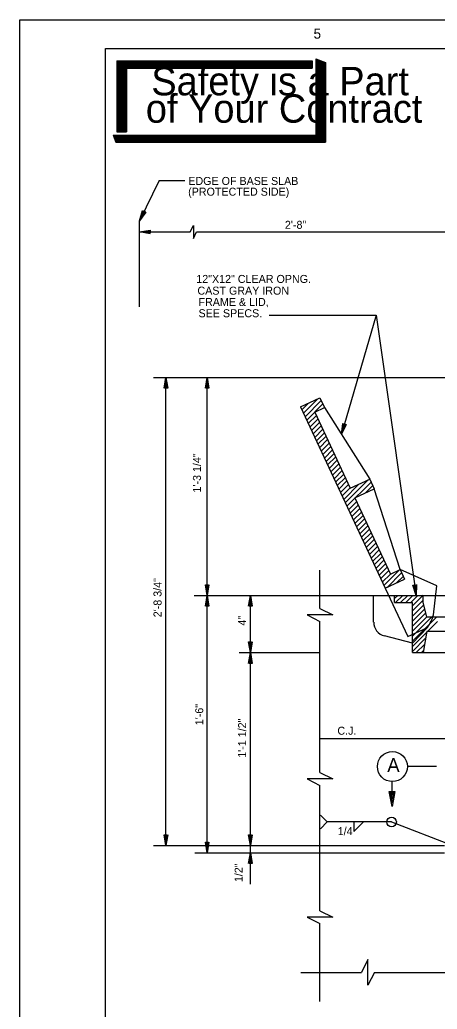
# Model space of a CAD drawing. Extents: x 0.1 to 13.5, y 0.1 to 9.5.
# Drawn here: x 0.13 to 2.56, y 3.69 to 9.46 of the extents above; entities that cross this region are included whole.
import ezdxf

# ---------------------------------------------------------------- set-up
doc = ezdxf.new("R2010")
doc.units = 0
for name, color, linetype in [('Level 1', 7, 'Continuous'), ('Level 13', 7, 'Continuous'), ('Level 2', 7, 'Continuous'), ('Level 25', 7, 'Continuous'), ('Level 3', 7, 'Continuous'), ('Level 50', 7, 'Continuous')]:
    doc.layers.add(name, color=color, linetype=linetype)

msp = doc.modelspace()

# ---------------------------------------------------------------- linework, layer by layer
at = {"layer": 'Level 1'}
for p, q in [((1.8506, 9.2306), (1.8506, 8.7859)), ((1.8506, 9.2306), (1.9063, 9.2099)), ((1.8543, 9.2292), (1.8543, 8.7442)), ((0.6906, 9.2182), (1.8296, 9.2182)), ((0.6906, 9.2182), (0.6906, 8.8046)), ((0.6906, 9.2129), (1.8296, 9.2129)), ((0.6906, 9.2079), (1.8296, 9.2079)), ((0.6906, 9.2026), (1.8296, 9.2026)), ((0.6906, 9.1972), (1.8296, 9.1972)), ((0.6906, 9.1922), (1.8296, 9.1922)), ((0.6906, 9.1869), (1.8296, 9.1869)), ((0.6906, 9.1819), (1.8296, 9.1819)), ((0.6959, 9.2182), (0.6959, 8.8046)), ((0.7009, 9.2182), (0.7009, 8.8046)), ((0.7063, 9.2182), (0.7063, 8.8046)), ((0.7113, 9.2182), (0.7113, 8.8046)), ((0.7166, 9.2182), (0.7166, 8.8046)), ((0.7219, 9.2182), (0.7219, 8.8046)), ((0.7269, 9.2182), (0.7269, 8.8046)), ((0.7323, 9.2182), (0.7323, 8.8046)), ((0.7376, 9.2182), (0.7376, 8.8046)), ((0.7426, 9.2182), (0.7426, 8.8046)), ((0.7463, 9.1766), (1.8296, 9.1766)), ((0.7463, 9.1766), (0.7463, 8.8046)), ((1.8296, 9.2182), (1.8296, 9.1766)), ((1.8593, 9.2272), (1.8593, 8.7442)), ((1.8646, 9.2252), (1.8646, 8.7442)), ((1.8699, 9.2232), (1.8699, 8.7442)), ((1.8749, 9.2216), (1.8749, 8.7442)), ((1.8803, 9.2196), (1.8803, 8.7442)), ((1.8853, 9.2176), (1.8853, 8.7442)), ((1.8906, 9.2156), (1.8906, 8.7442)), ((1.8959, 9.2139), (1.8959, 8.7442)), ((1.9009, 9.2099), (1.9009, 8.7442)), ((1.9063, 9.2099), (1.9063, 8.7442)), ((0.6696, 8.7859), (1.8506, 8.7859)), ((0.6696, 8.7859), (0.6849, 8.7442)), ((0.6716, 8.7806), (1.8543, 8.7806)), ((0.6733, 8.7756), (1.8543, 8.7756)), ((0.6753, 8.7702), (1.8543, 8.7702)), ((0.6906, 8.8046), (0.7463, 8.8046)), ((0.6773, 8.7649), (1.8543, 8.7649)), ((0.6793, 8.7599), (1.8543, 8.7599)), ((0.6813, 8.7546), (1.8543, 8.7546)), ((0.6829, 8.7496), (1.8543, 8.7496)), ((0.6849, 8.7442), (1.9063, 8.7442))]:
    msp.add_line(p, q, dxfattribs=at)
for points in [[(0.125, 9.4583), (13.4583, 9.4583), (13.4583, 0.125), (0.125, 0.125)], [(0.625, 9.2917), (13.2917, 9.2917), (13.2917, 0.2917), (0.625, 0.2917)]]:
    msp.add_lwpolyline(points, close=True, dxfattribs=at)
at = {"layer": 'Level 13'}
for points in [[(1.1179, 8.2214), (1.1365, 8.2589), (1.1365, 8.184), (1.1553, 8.2214)], [(1.8741, 6.0263), (1.9491, 5.989), (1.7993, 5.989), (1.8741, 5.9515)], [(1.8741, 5.0704), (1.9491, 5.0332), (1.7993, 5.0332), (1.8741, 4.9957)], [(1.8741, 4.2652), (1.9491, 4.228), (1.7993, 4.228), (1.8741, 4.1905)], [(2.1915, 3.9056), (2.1542, 3.8306), (2.1542, 3.9805), (2.1167, 3.9056)]]:
    msp.add_lwpolyline(points, dxfattribs=at)
at = {"layer": 'Level 25'}
for p, q in [((0.9378, 8.5209), (0.8229, 8.2865)), ((0.9378, 8.5209), (1.0873, 8.5209)), ((0.8229, 7.7843), (0.8229, 8.2865)), ((0.8229, 8.2214), (1.1179, 8.2214)), ((1.1553, 8.2214), (3.0596, 8.2214)), ((1.5787, 7.7375), (2.202, 7.7375)), ((2.202, 7.7375), (1.9993, 7.0424)), ((2.202, 7.7375), (2.4353, 6.1027)), ((0.9038, 7.3735), (2.6846, 7.3735)), ((0.9766, 4.6444), (0.9766, 7.3735)), ((1.2169, 6.1027), (1.2169, 7.3735)), ((1.7614, 7.2017), (1.8747, 7.2545)), ((1.8073, 7.2231), (1.7692, 7.185)), ((1.8625, 7.2488), (1.7786, 7.1649)), ((1.882, 7.2389), (1.788, 7.1448)), ((1.8914, 7.2188), (1.7973, 7.1248)), ((1.8747, 7.2545), (1.9011, 7.1979)), ((1.7614, 7.2017), (2.2545, 6.1444)), ((1.8537, 7.1517), (1.8067, 7.1047)), ((1.8445, 7.1715), (1.9011, 7.1979)), ((1.8445, 7.1715), (1.8684, 7.1203)), ((1.8445, 7.1715), (2.0514, 6.7278)), ((1.9011, 7.1979), (2.1647, 6.7806)), ((1.8631, 7.1316), (1.8161, 7.0846)), ((1.8725, 7.1115), (1.8254, 7.0645)), ((1.8819, 7.0914), (1.8348, 7.0444)), ((1.8912, 7.0713), (1.8442, 7.0243)), ((1.9006, 7.0512), (1.8535, 7.0042)), ((1.91, 7.0311), (1.8629, 6.9841)), ((1.9193, 7.0111), (1.8723, 6.964)), ((1.9287, 6.991), (1.8816, 6.9439)), ((1.9381, 6.9709), (1.891, 6.9238)), ((1.9474, 6.9508), (1.9004, 6.9037)), ((1.9568, 6.9307), (1.9098, 6.8836)), ((1.9662, 6.9106), (1.9191, 6.8635)), ((1.9755, 6.8905), (1.9285, 6.8435)), ((1.9849, 6.8704), (1.9379, 6.8234)), ((1.9943, 6.8503), (1.9472, 6.8033)), ((2.0036, 6.8302), (1.9566, 6.7832)), ((2.013, 6.8101), (1.966, 6.7631)), ((2.0224, 6.79), (1.9753, 6.743)), ((2.0318, 6.7699), (1.9847, 6.7229)), ((2.0411, 6.7498), (1.9941, 6.7028)), ((2.1012, 6.751), (2.0128, 6.6626)), ((2.1564, 6.7767), (2.0222, 6.6425)), ((2.1726, 6.7635), (2.0316, 6.6224)), ((2.0514, 6.7278), (2.1647, 6.7806)), ((2.1647, 6.7806), (2.1911, 6.7239)), ((2.0505, 6.7298), (2.0035, 6.6827)), ((2.0778, 6.6711), (2.1911, 6.7239)), ((2.182, 6.7434), (2.1376, 6.699)), ((2.3413, 6.2538), (2.1911, 6.7239)), ((2.088, 6.6494), (2.0409, 6.6023)), ((2.0778, 6.6711), (2.2847, 6.2274)), ((2.0973, 6.6293), (2.0503, 6.5823)), ((2.1067, 6.6092), (2.0597, 6.5622)), ((2.1161, 6.5891), (2.069, 6.5421)), ((2.1254, 6.569), (2.0784, 6.522)), ((2.1348, 6.5489), (2.0878, 6.5019)), ((2.1442, 6.5288), (2.0971, 6.4818)), ((2.1535, 6.5087), (2.1065, 6.4617)), ((2.1629, 6.4886), (2.1159, 6.4416)), ((2.1723, 6.4685), (2.1253, 6.4215)), ((2.1816, 6.4484), (2.1346, 6.4014)), ((2.191, 6.4283), (2.144, 6.3813)), ((2.2004, 6.4082), (2.1534, 6.3612)), ((2.2098, 6.3882), (2.1627, 6.3411)), ((2.2191, 6.3681), (2.1721, 6.321)), ((2.2285, 6.348), (2.1815, 6.3009)), ((2.2379, 6.3279), (2.1908, 6.2809)), ((2.2472, 6.3078), (2.2002, 6.2608)), ((2.2566, 6.2877), (2.2096, 6.2407)), ((1.8741, 6.0263), (1.8741, 6.2501)), ((2.266, 6.2676), (2.2189, 6.2206)), ((2.2753, 6.2475), (2.2283, 6.2005)), ((2.3399, 6.2531), (2.2471, 6.1603)), ((2.3505, 6.2342), (2.2659, 6.1497)), ((2.2847, 6.2274), (2.3413, 6.2538)), ((2.3413, 6.2538), (2.3678, 6.1972)), ((2.5561, 6.1592), (2.3413, 6.2538)), ((2.2847, 6.2274), (2.2377, 6.1804)), ((2.2545, 6.1444), (2.3678, 6.1972)), ((2.3598, 6.2141), (2.3211, 6.1754)), ((2.2545, 6.1444), (2.3859, 5.8625)), ((2.5363, 5.9897), (2.5561, 6.1592)), ((1.1421, 6.1027), (1.8741, 6.1027)), ((1.2169, 4.6027), (1.2169, 6.1027)), ((1.4687, 5.7694), (1.4687, 6.1027)), ((1.8741, 6.1027), (2.4763, 6.1027)), ((2.1875, 5.9471), (2.1875, 6.1027)), ((2.3096, 6.061), (2.3096, 6.1027)), ((2.3275, 6.1027), (2.3096, 6.0848)), ((2.3096, 6.061), (2.4138, 6.061)), ((2.357, 6.1027), (2.3153, 6.061)), ((2.3864, 6.1027), (2.3448, 6.061)), ((2.4159, 6.1027), (2.3742, 6.061)), ((2.4454, 6.1027), (2.4037, 6.061)), ((2.4763, 6.1042), (2.4138, 6.0417)), ((2.4763, 6.0747), (2.4138, 6.0122)), ((2.4138, 5.7694), (2.4138, 6.061)), ((2.4763, 6.061), (2.4763, 6.1027)), ((2.4763, 6.1027), (2.5495, 6.1027)), ((2.4971, 5.9777), (2.4763, 6.061)), ((2.5495, 6.1027), (2.6846, 6.1027)), ((2.4795, 6.0484), (2.4138, 5.9828)), ((2.4854, 6.0248), (2.4138, 5.9533)), ((2.4913, 6.0013), (2.4138, 5.9238)), ((1.8741, 5.0704), (1.8741, 5.9515)), ((2.4971, 5.9777), (2.4138, 5.8944)), ((2.5266, 5.9777), (2.4138, 5.8649)), ((2.5561, 5.9777), (2.4138, 5.8354)), ((2.5596, 5.9518), (2.4138, 5.806)), ((2.4971, 5.9777), (2.6846, 5.9777)), ((2.3859, 5.8625), (2.5021, 5.9166)), ((2.4135, 5.824), (2.5021, 5.9166)), ((2.4971, 5.8944), (2.4763, 5.7694)), ((2.4971, 5.8944), (2.6846, 5.8944)), ((2.4135, 5.824), (2.2499, 5.8665)), ((2.4902, 5.8529), (2.4138, 5.7765)), ((1.4034, 5.7694), (1.8741, 5.7694)), ((1.4687, 4.6444), (1.4687, 5.7694)), ((2.4138, 5.7694), (2.6846, 5.7694)), ((2.4843, 5.8176), (2.4361, 5.7694)), ((2.4785, 5.7822), (2.4656, 5.7694)), ((1.8741, 5.2694), (5.7074, 5.2694)), ((1.8741, 4.2652), (1.8741, 4.9957)), ((1.9167, 4.7824), (1.8769, 4.8223)), ((1.9167, 4.7824), (1.8769, 4.7427)), ((2.2918, 4.7824), (1.9167, 4.7824)), ((2.0722, 4.783), (2.0722, 4.7268)), ((2.0722, 4.7268), (2.128, 4.7826)), ((2.2918, 4.7824), (2.643, 4.647)), ((0.9038, 4.6444), (2.6013, 4.6444)), ((1.4687, 4.6027), (1.4687, 4.6444)), ((1.1453, 4.6027), (2.6013, 4.6027)), ((1.4687, 4.4202), (1.4687, 4.6027)), ((1.8741, 3.7351), (1.8741, 4.1905)), ((1.7622, 3.9056), (2.1167, 3.9056)), ((2.1915, 3.9056), (3.1524, 3.9056))]:
    msp.add_line(p, q, dxfattribs=at)
msp.add_circle((2.2918, 4.7824), 0.0281, dxfattribs=at)
for centre, radius, start, end in [((2.2709, 5.9471), 0.0833, 180, 255.43423), ((2.2735, 6.0684), 0.2744, 326.4322, 343.33101)]:
    msp.add_arc(centre, radius, start, end, dxfattribs=at)
at = {"layer": 'Level 3'}
for p, q in [((2.5544, 5.1051), (2.3823, 5.1051)), ((2.2949, 4.9593), (2.2949, 5.0176))]:
    msp.add_line(p, q, dxfattribs=at)
msp.add_lwpolyline([(2.3072, 4.9593), (2.3115, 4.9593), (2.2949, 4.8718), (2.2786, 4.9593), (2.3072, 4.9593), (2.2952, 4.8941), (2.2835, 4.9551), (2.3024, 4.9551), (2.2952, 4.9161), (2.2887, 4.951), (2.2974, 4.951), (2.2952, 4.9385), (2.2936, 4.9468)], dxfattribs=at)
msp.add_circle((2.2966, 5.1051), 0.0875, dxfattribs=at)
at = {"layer": 'Level 50'}
for p, q in [((0.8229, 8.2865), (0.8229, 8.2865)), ((0.8305, 8.302), (0.8305, 8.302)), ((0.8229, 8.2214), (0.8229, 8.2214)), ((0.8403, 8.2214), (0.8403, 8.2214)), ((0.9766, 7.3735), (0.9766, 7.3735)), ((0.9766, 7.3562), (0.9766, 7.3562)), ((1.2169, 7.3735), (1.2169, 7.3735)), ((1.2169, 7.3562), (1.2169, 7.3562)), ((1.9993, 7.0424), (1.9993, 7.0424)), ((2.0042, 7.059), (2.0042, 7.059)), ((1.2169, 6.12), (1.2169, 6.12)), ((2.4329, 6.1199), (2.4329, 6.1199)), ((1.2169, 6.1027), (1.2169, 6.1027)), ((1.2169, 6.1027), (1.2169, 6.1027)), ((1.2169, 6.0854), (1.2169, 6.0854)), ((1.4687, 6.1027), (1.4687, 6.1027)), ((1.4687, 6.0854), (1.4687, 6.0854)), ((2.4353, 6.1027), (2.4353, 6.1027)), ((1.4687, 5.7867), (1.4687, 5.7867)), ((1.4687, 5.7694), (1.4687, 5.7694)), ((1.4687, 5.7694), (1.4687, 5.7694)), ((1.4687, 5.752), (1.4687, 5.752)), ((0.9766, 4.6617), (0.9766, 4.6617)), ((0.9766, 4.6444), (0.9766, 4.6444)), ((1.2169, 4.62), (1.2169, 4.62)), ((1.4687, 4.6617), (1.4687, 4.6617)), ((1.4687, 4.6444), (1.4687, 4.6444)), ((1.2169, 4.6027), (1.2169, 4.6027)), ((1.4687, 4.6027), (1.4687, 4.6027)), ((1.4687, 4.5854), (1.4687, 4.5854))]:
    msp.add_line(p, q, dxfattribs=at)
for points in [[(0.8596, 8.3379), (0.8229, 8.2865), (0.8411, 8.347), (0.8569, 8.3392), (0.8305, 8.302), (0.8429, 8.3431), (0.8531, 8.3381), (0.8379, 8.317), (0.8447, 8.3393), (0.8489, 8.3372), (0.8455, 8.3326)], [(0.8853, 8.2111), (0.8229, 8.2214), (0.8853, 8.2318), (0.8853, 8.2141), (0.8403, 8.2214), (0.8826, 8.2284), (0.8826, 8.2171), (0.8569, 8.2214), (0.8799, 8.2251), (0.8799, 8.2204), (0.8743, 8.2214)], [(0.9663, 7.3112), (0.9766, 7.3735), (0.9869, 7.3112), (0.9693, 7.3112), (0.9766, 7.3562), (0.9836, 7.3139), (0.9723, 7.3139), (0.9766, 7.3395), (0.9803, 7.3165), (0.9756, 7.3165), (0.9766, 7.3222)], [(1.2066, 7.3112), (1.2169, 7.3735), (1.2273, 7.3112), (1.2096, 7.3112), (1.2169, 7.3562), (1.2239, 7.3139), (1.2126, 7.3139), (1.2169, 7.3395), (1.2206, 7.3165), (1.2159, 7.3165), (1.2169, 7.3222)], [(2.0267, 7.0993), (1.9993, 7.0424), (2.0069, 7.1051), (2.0238, 7.1002), (2.0042, 7.059), (2.0093, 7.1016), (2.0202, 7.0984), (2.0089, 7.075), (2.0118, 7.0981), (2.0163, 7.0968), (2.0137, 7.0917)], [(1.2273, 6.165), (1.2169, 6.1027), (1.2066, 6.165), (1.2243, 6.165), (1.2169, 6.12), (1.2099, 6.1624), (1.2213, 6.1624), (1.2169, 6.1367), (1.2133, 6.1597), (1.2179, 6.1597), (1.2169, 6.154)], [(2.4368, 6.1659), (2.4353, 6.1027), (2.4163, 6.1629), (2.4338, 6.1654), (2.4329, 6.1199), (2.42, 6.1608), (2.4312, 6.1624), (2.4305, 6.1364), (2.4237, 6.1586), (2.4283, 6.1593), (2.4281, 6.1535)], [(1.2066, 6.0404), (1.2169, 6.1027), (1.2273, 6.0404), (1.2096, 6.0404), (1.2169, 6.0854), (1.2239, 6.043), (1.2126, 6.043), (1.2169, 6.0687), (1.2206, 6.0457), (1.2159, 6.0457), (1.2169, 6.0514)], [(1.4584, 6.0404), (1.4687, 6.1027), (1.479, 6.0404), (1.4614, 6.0404), (1.4687, 6.0854), (1.4757, 6.043), (1.4644, 6.043), (1.4687, 6.0687), (1.4724, 6.0457), (1.4677, 6.0457), (1.4687, 6.0514)], [(1.479, 5.8317), (1.4687, 5.7694), (1.4584, 5.8317), (1.476, 5.8317), (1.4687, 5.7867), (1.4617, 5.829), (1.473, 5.829), (1.4687, 5.8034), (1.465, 5.8264), (1.4697, 5.8264), (1.4687, 5.8207)], [(1.4584, 5.707), (1.4687, 5.7694), (1.479, 5.707), (1.4614, 5.707), (1.4687, 5.752), (1.4757, 5.7097), (1.4644, 5.7097), (1.4687, 5.7354), (1.4724, 5.7124), (1.4677, 5.7124), (1.4687, 5.718)], [(0.9869, 4.7067), (0.9766, 4.6444), (0.9663, 4.7067), (0.9839, 4.7067), (0.9766, 4.6617), (0.9696, 4.704), (0.9809, 4.704), (0.9766, 4.6784), (0.9729, 4.7014), (0.9776, 4.7014), (0.9766, 4.6957)], [(1.479, 4.7067), (1.4687, 4.6444), (1.4584, 4.7067), (1.476, 4.7067), (1.4687, 4.6617), (1.4617, 4.704), (1.473, 4.704), (1.4687, 4.6784), (1.465, 4.7014), (1.4697, 4.7014), (1.4687, 4.6957)], [(1.2273, 4.665), (1.2169, 4.6027), (1.2066, 4.665), (1.2243, 4.665), (1.2169, 4.62), (1.2099, 4.6624), (1.2213, 4.6624), (1.2169, 4.6367), (1.2133, 4.6597), (1.2179, 4.6597), (1.2169, 4.654)], [(1.4584, 4.5404), (1.4687, 4.6027), (1.479, 4.5404), (1.4614, 4.5404), (1.4687, 4.5854), (1.4757, 4.543), (1.4644, 4.543), (1.4687, 4.5687), (1.4724, 4.5457), (1.4677, 4.5457), (1.4687, 4.5514)]]:
    msp.add_lwpolyline(points, dxfattribs=at)

# ---------------------------------------------------------------- texts
at = {"layer": 'Level 1'}
for s, height, p in [('5', 0.0584, (1.8373, 9.3483)), ('Safety is a Part', 0.165583, (0.8916, 9.018)), ('of Your Contract', 0.165583, (0.8594, 8.8584))]:
    msp.add_text(s, height=height, dxfattribs=at).set_placement(p)
at = {"layer": 'Level 2'}
msp.add_text('A', height=0.08, dxfattribs=at).set_placement((2.2671, 5.0744))
at = {"layer": 'Level 25'}
for s, height, p in [('EDGE OF BASE SLAB', 0.046667, (1.1072, 8.4956)), ('(PROTECTED SIDE)', 0.046667, (1.1062, 8.433)), ('2\'-8"', 0.04667, (1.6703, 8.2398)), ('12"X12" CLEAR OPNG.', 0.046667, (1.1537, 7.9244)), ('CAST GRAY IRON', 0.046667, (1.1604, 7.8561)), ('FRAME & LID,', 0.046667, (1.1666, 7.7901)), ('SEE SPECS.', 0.04667, (1.1667, 7.7244)), ('C.J.', 0.04667, (1.9762, 5.2908)), ('1/4', 0.04667, (1.9781, 4.7056))]:
    msp.add_text(s, height=height, dxfattribs=at).set_placement(p)
for s, p in [('1\'-3 1/4"', (1.1808, 6.7026)), ('2\'-8 3/4"', (0.9511, 5.9755)), ('4"', (1.4442, 5.9272)), ('1\'-6"', (1.1943, 5.3461)), ('1\'-1 1/2"', (1.4442, 5.1564)), ('1/2"', (1.424, 4.4316))]:
    msp.add_text(s, height=0.04667, rotation=90, dxfattribs=at).set_placement(p)

doc.saveas('drawing.dxf')
